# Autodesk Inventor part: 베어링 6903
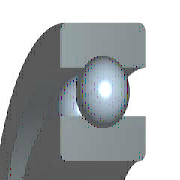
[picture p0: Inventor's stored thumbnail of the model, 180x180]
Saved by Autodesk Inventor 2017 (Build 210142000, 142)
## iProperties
Created: 2012-02
Part Number: 베어링 6903
Material: 강철, 연강
Description: 깊은 그루브 볼 베어링
Document SubType Name: Modeling
Standard: KS B 2023
Designer: mduedu
Standards Organization: KS
Language: ko-KR
Size Designation: 6003 - 17 x 35 x 10
Categories: <MemberInstance><Categories><Category DisplayName="샤프트 부품" InternalName="7f7aeb1f-a693-4053-b835-cee3144e0d98" Mnemonic="SHFT"><Category DisplayName="베어링" Inter
Density: 7.86 g/cm^3
Appearance: 터키옥색
Mass: 17.7898 g
Surface Area: 30.969 cm^2
Volume: 2.26333 cm^3
IsCustomPart: 1
Author: mduedu
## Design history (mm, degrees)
sketch "스케치" dims "d0" = 3.38 (= -0.26 x WD + 0.26 x BD)
  geometry: L1 (1.81, 11.75)-(5.19, 11.75); L2 (3.5, 11.75)-(3.5, 10.06); L3 (3.5, 11.75)-(3.5, 13.44); L4 (2.244, 10.619)-(0, 10.619); L5 (0, 8.5)-(7, 8.5); L6 (2.244, 12.881)-(0, 12.881); L7 (0, 15)-(7, 15); L8 (7, 8.5)-(7, 10.619); L9 (4.756, 10.619)-(7, 10.619); L10 (4.756, 12.881)-(7, 12.881); L11 (7, 15)-(7, 12.881); L12 (-2, 0)-(12, 0) reference; L13 (0, 7.2)-(0, 16.3) reference; 1 other entity
  constraints: 22 end point, 4 point on line, 2 collinear, 2 perpendicular, 2 symmetric about line, 1 midpoint, 1 parallel, 14 other
  dimensions: "d9" = 17 diameter of L5 L12 (= WD); "d11" = 30 diameter of L7 L12 (= BD); "d12" = 7 distance between parallel lines of L8 L13 (= KB); "d13" = 21.238 diameter of L9 L12 (= 0.326 x BD + 0.674 x WD)
revolve "본체" stored, may be unused: angle "d6" = 90 deg
revolve "볼" stored, may be unused: angle "d7" = 90 deg
pattern_circular "IDS_ARRAYBALL[SIMPL:T]" dims angle "d3" = 360 deg
body "Solid1"
fillet "모깎기1" dims "d1" = 0.3 (= KRS)
other parameters: "WD" = 17 [user parameter; used in 5 equation terms], "BD" = 30 [user parameter; used in 5 equation terms], "KB" = 7 [user parameter; used in 1 equation term], "KRS" = 0.3 [user parameter; used in 1 equation term], "d4" = 0, "d5" = 0, "d8" = 0, "d14" = 0, "d15" = 0, "BBA" = 0 [user parameter], "BC0" = 3250000 [user parameter], "BC" = 6050000 [user parameter], "BR" = 15 (= 0.5 x BD) [user parameter], "WR" = 8.5 (= 0.5 x WD) [user parameter]
